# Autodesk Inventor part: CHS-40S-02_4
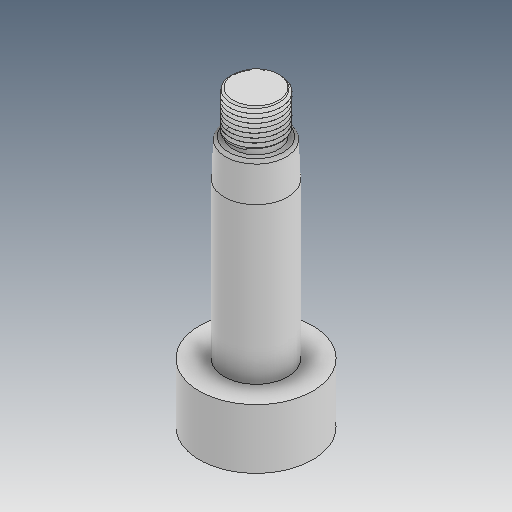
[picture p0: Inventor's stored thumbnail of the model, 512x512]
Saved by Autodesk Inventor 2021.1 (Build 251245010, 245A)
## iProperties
Created: 2019-04
Part Number: CHS-40S-02_4
Material: Ogólny
Document SubType Name: Modeling
Designer: user
Density: 1 g/cm^3
Appearance: Domyślna
Author: user
Revision Number: ÈÎºÎ
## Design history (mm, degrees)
feature "ÊäÈë1"
feature "ÊäÈë2"
node "Bryła1"
node "Bryła2"
